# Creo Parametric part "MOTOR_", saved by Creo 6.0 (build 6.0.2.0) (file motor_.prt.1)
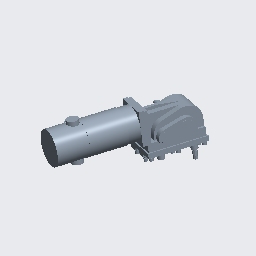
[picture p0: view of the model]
Units: millimeter Newton Second (mmNs); MM, TONNE, SECS

Created from: MOTOR_REAL.PRT

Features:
  1. datum plane "RIGHT"
  2. datum plane "TOP"
  3. datum plane "FRONT"
  4. coordinate system
  5. curve
  6. protrusion
  7. curve
  8. protrusion
  9. curve
  10. protrusion
  11. curve
  12. protrusion
  13. curve
  14. protrusion
  15. curve
  16. protrusion
  17. curve
  18. protrusion
  19. curve
  20. protrusion
  21. curve
  22. protrusion
  23. round
  24. round
  25. curve
  26. protrusion
  27. curve
  28. curve
  29. protrusion
  30. curve
  31. protrusion
  32. sketch "Sketch 14"
  33. extrusion "Extrude 13"
  34. sketch "Sketch 15"
  35. extrusion "Extrude 14"
  36. extrusion "Extrude 15"
  37. sketch "Sketch 16"
  38. extrusion "Extrude 16"
  39. sketch "Sketch 17"
  40. extruded cut "Extrude 17"
  41. sketch "Sketch 18"
  42. extrusion "Extrude 18"
  43. sketch "Sketch 19"
  44. extrusion "Extrude 19"
  45. sketch "Sketch 20"
  46. extrusion "Extrude 20"
  47. sketch "Sketch 21"
  48. extrusion "Extrude 21"
  49. sketch "Sketch 22"
  50. extrusion "Extrude 22"
  51. sketch "Sketch 23"
  52. extrusion "Extrude 23"
  53. sketch "Sketch 24"
  54. extrusion "Extrude 24"
  55. sketch "Sketch 25"
  56. extruded cut "Extrude 25"
  57. sketch "Sketch 26"
  58. extrusion "Extrude 26"
  59. sketch "Sketch 27"
  60. extrusion "Extrude 27"
  61. sketch "Sketch 28"
  62. extruded cut "Extrude 28"
  63. sketch "Sketch 29"
  64. extrusion "Extrude 29"

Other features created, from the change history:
  sketch "Sketch 23"

Surfaces: 66 plane, 46 cylinder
